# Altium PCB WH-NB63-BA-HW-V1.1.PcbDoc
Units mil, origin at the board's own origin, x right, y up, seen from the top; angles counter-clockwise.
Board outline 6000 x 4000 mil, 6 copper layers (Top-L1, Inner Layer-L2, Gnd-L3, Powr-L4, Inner Layer 5, Bot-L6), stack 45.4 mil thick; 1 components, 0 nets, 42 pads, 0 vias.
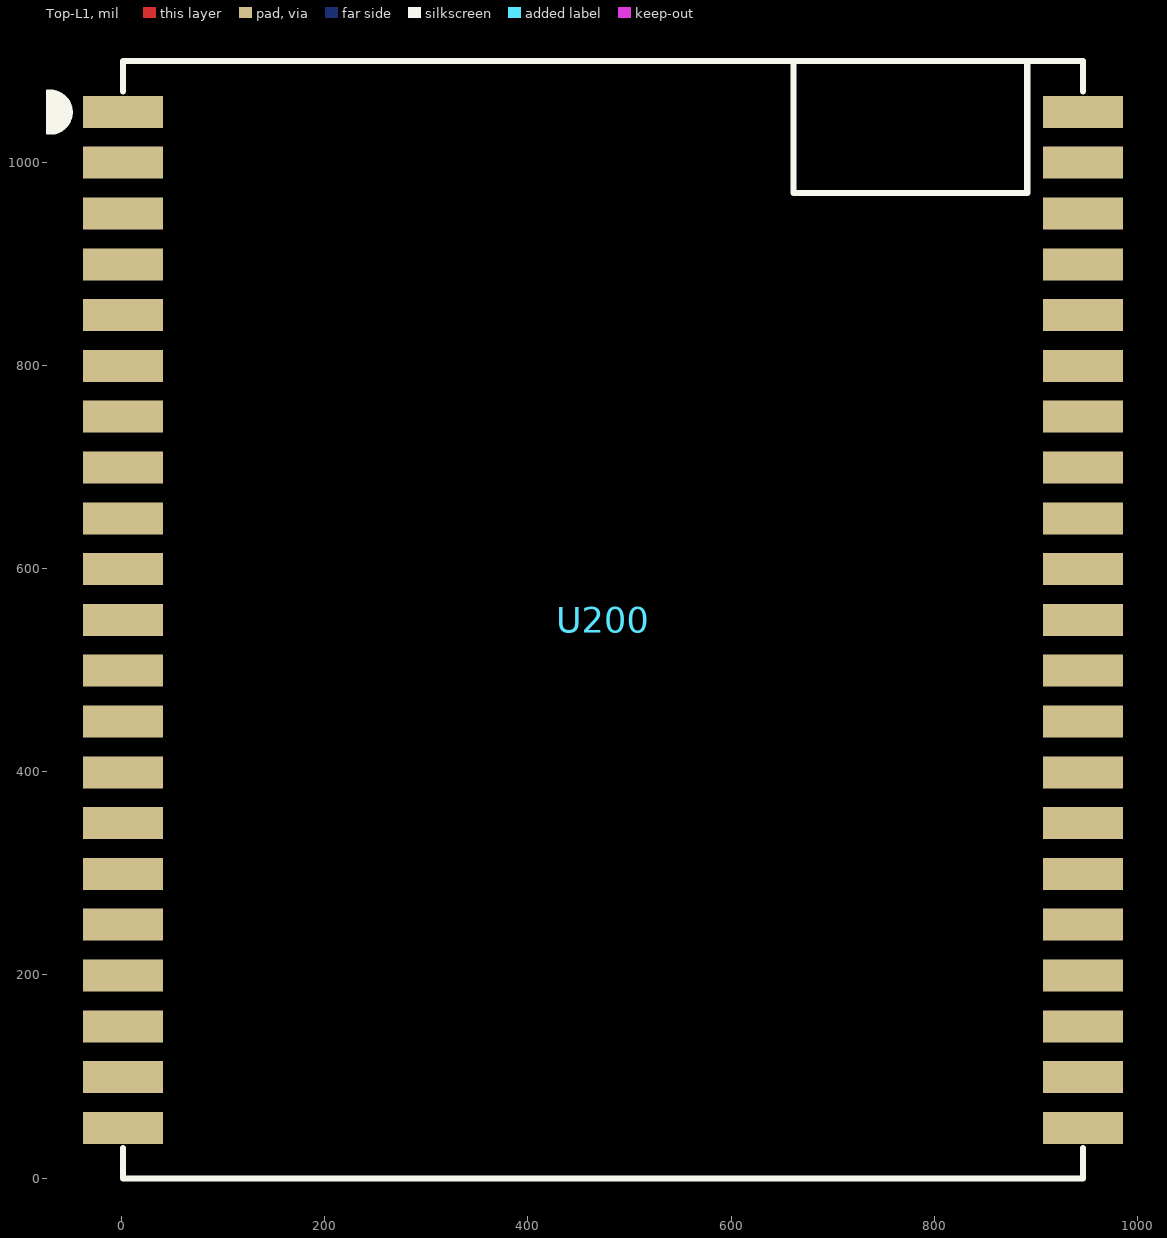
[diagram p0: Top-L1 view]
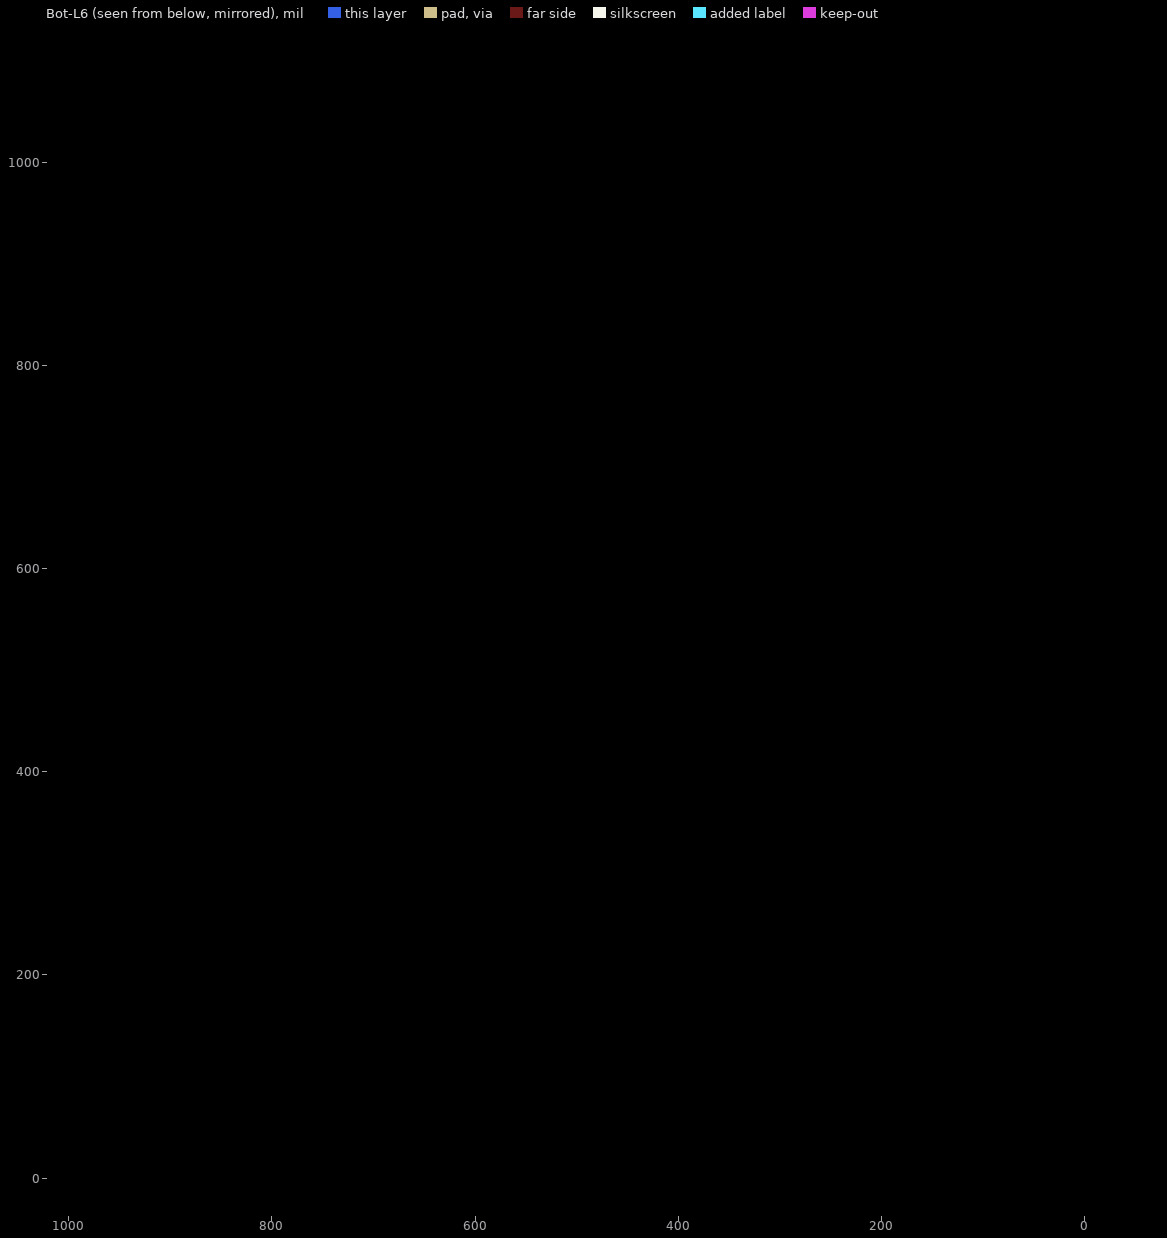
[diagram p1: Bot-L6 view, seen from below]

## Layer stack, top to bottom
Solder Mask Top: solder mask 0.4, Solder Resist, Dk 3.5
Top-L1: signal copper (thickness not stored)
Inner Layer-L2: signal copper 1.35
Dielectric2: dielectric 10, FR-4, Dk 4.3
Gnd-L3: signal copper 1.35
Dielectric3: dielectric 10, FR-4, Dk 4.3
Powr-L4: signal copper 1.35
Dielectric4: dielectric 10, FR-4, Dk 4.3
Inner Layer 5: signal copper 1.35
Dielectric5: dielectric 10, FR-4, Dk 4.3
Bot-L6: signal copper (thickness not stored)
Solder Mask Bot: solder mask 0.4, Solder Resist, Dk 3.5

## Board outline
-33671.27,-31166.98 -27671.27,-31166.98 -27671.27,-27166.98 -33671.27,-27166.98

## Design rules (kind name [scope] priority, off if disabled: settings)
Clearance "Clearance - Default - DEFAULT- SMD" [IsVia vs IsSMTPin] p1: gap=0 ignorepadtopadclearanceinfootprint=FALSE
Clearance "Clearance - Default - DEFAULT - Via" [IsVia vs IsVia] p2: gap=0 ignorepadtopadclearanceinfootprint=FALSE
Clearance "Clearance - Default - DEFAULT - Net" [All] p3: gap=3 ignorepadtopadclearanceinfootprint=FALSE except(0: Arc-Hole Track-Hole SMDPad-Hole THPad-Hole Via-Hole Fill-Hole Poly-Hole Region-Hole Text-Hole; 3.94: SMDPad-Fill SMDPad-Poly SMDPad-Region THPad-Fill THPad-Poly THPad-Region Via-Fill Via-Poly Via-Region; 10: Text-Text)
ComponentClearance "ComponentClearance - Default - _1" [All] p1: gap=0 collisioncheckmode=3 verticalgap=10 showdistances=FALSE
ComponentClearance "ComponentClearance - Default -" [All] p2: gap=0 collisioncheckmode=3 verticalgap=10 showdistances=FALSE
ComponentClearance "ComponentClearance - Default - DEFAULT" [All] p3: gap=0 collisioncheckmode=3 verticalgap=10 showdistances=FALSE
FanoutControl Fanout_LCC [IsLCC] p1: bgadir=Out bgaviamode=Centered fanoutstyle=Auto fanoutdirection=Alternating viagrid=1 // Fanout_LCC (Default Rule)
FanoutControl Fanout_BGA [IsBGA] p2: bgadir=Out bgaviamode=Centered fanoutstyle=Auto fanoutdirection=Alternating viagrid=1 // Fanout_BGA (Default Rule)
FanoutControl Fanout_Small [(CompPinCount < 5)] p3: bgadir=Out bgaviamode=Centered fanoutstyle=Auto fanoutdirection=OutThenIn viagrid=1 // Fanout_Small (Default Rule)
FanoutControl Fanout_SOIC [IsSOIC] p4: bgadir=Out bgaviamode=Centered fanoutstyle=Auto fanoutdirection=Alternating viagrid=1 // Fanout_SOIC (Default Rule)
HoleToHoleClearance "HoleToHoleClearance - Default - DEFAULT" [All] p1: gap=0 allowstackedmicrovias=TRUE
Length "Default Length" [All] p1: maxlimit=50000 minlimit=0
MaxMinImpedance "Default Impedance" [All] p1: minimum=50.00 maximum=150.0
ParallelSegment "Default Parallel Segment Same Layer" [All] p1: limit=1000 gap=200
ParallelSegment "Default Parallel Segment Adjasent" [All] p2: limit=1000 gap=200
PlaneConnect "Default PlaneConnect" [All] p1: planeconnectstyle=Direct reliefexpansion=20 reliefentries=4 reliefconductorwidth=11.81 reliefairgap=10
PolygonConnect "PolygonConnect - Default SMT" [IsSMTPin] p1: connectstyle=Direct reliefconductorwidth=9.84 reliefentries=4 polygonreliefangle="45 Angle" airgapwidth=10
PolygonConnect "PolygonConnect - Default Pad" [All] p2: connectstyle=Direct reliefconductorwidth=11.81 reliefentries=4 polygonreliefangle="45 Angle" airgapwidth=10
RoutingLayers "RoutingLayers - Default - DEFAULT" [All] p1: top layer_v5=TRUE mid layer 1_v5=TRUE mid layer 2_v5=TRUE mid layer 3_v5=TRUE mid layer 4_v5=TRUE bottom layer_v5=TRUE
RoutingPriority "RoutingPriority - Default - DEFAULT" [All] p1: routingpriority=3
RoutingTopology "Default Routing Topology" [All] p1: topology=Shortest
RoutingVias [All] p1: holewidth=28 width=50 viastyle="Through Hole" minholewidth=28 minwidth=50 maxholewidth=28 maxwidth=50
SMDToCorner "SMDToCorner - Default - DEFAULT" [All] p1: distance=0
SolderMaskExpansion [All] p1: expansion=4
Width "Default Width" [All] p1: maxlimit=78.74 minlimit=3 preferedwidth=3.94
Width "Default Width_1" [All] p2: maxlimit=78.74 minlimit=2.99 preferedwidth=3
20 further rules are at their usual default settings.

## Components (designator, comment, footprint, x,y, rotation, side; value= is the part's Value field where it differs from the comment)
U200 "NB63-I$2F$O" NB63-I$2F$O 474,549.36 r0 top

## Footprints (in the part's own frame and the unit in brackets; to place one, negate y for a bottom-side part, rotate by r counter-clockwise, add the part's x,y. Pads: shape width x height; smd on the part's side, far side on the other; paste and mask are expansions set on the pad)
NB63-I$2F$O [mm]
  rect 2x0.8 smd mask+0.051: 1(-12,12.7) 2(-12,11.43) 3(-12,10.16) 4(-12,8.89) 5(-12,7.62) 6(-12,6.35) 7(-12,5.08) 8(-12,3.81) 9(-12,2.54) 10(-12,1.27) 11(-12,0) 12(-12,-1.27) 13(-12,-2.54) 14(-12,-3.81) 15(-12,-5.08) 16(-12,-6.35) 17(-12,-7.62) 18(-12,-8.89) 19(-12,-10.16) 20(-12,-11.43) 21(-12,-12.7) 22(12,-12.7) 23(12,-11.43) 24(12,-10.16) 25(12,-8.89) 26(12,-7.62) 27(12,-6.35) 28(12,-5.08) 29(12,-3.81) 30(12,-2.54) 31(12,-1.27) 32(12,0) 33(12,1.27) 34(12,2.54) 35(12,3.81) 36(12,5.08) 37(12,6.35) 38(12,7.62) 39(12,8.89) 40(12,10.16) 41(12,11.43) 42(12,12.7)
  silkscreen extent -14.1,-13.97 12,13.97

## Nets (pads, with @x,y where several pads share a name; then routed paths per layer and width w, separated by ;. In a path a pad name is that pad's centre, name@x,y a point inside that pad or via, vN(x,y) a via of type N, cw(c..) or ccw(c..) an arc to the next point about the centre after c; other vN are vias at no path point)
pads on no net: U200.1 U200.2 U200.3 U200.4 U200.5 U200.6 U200.7 U200.8 U200.9 U200.10 U200.11 U200.12 U200.13 U200.14 U200.15 U200.16 U200.17 U200.18 U200.19 U200.20 U200.21 U200.22 U200.23 U200.24 U200.25 U200.26 U200.27 U200.28 U200.29 U200.30 U200.31 U200.32 U200.33 U200.34 U200.35 U200.36 U200.37 U200.38 U200.39 U200.40 U200.41 U200.42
